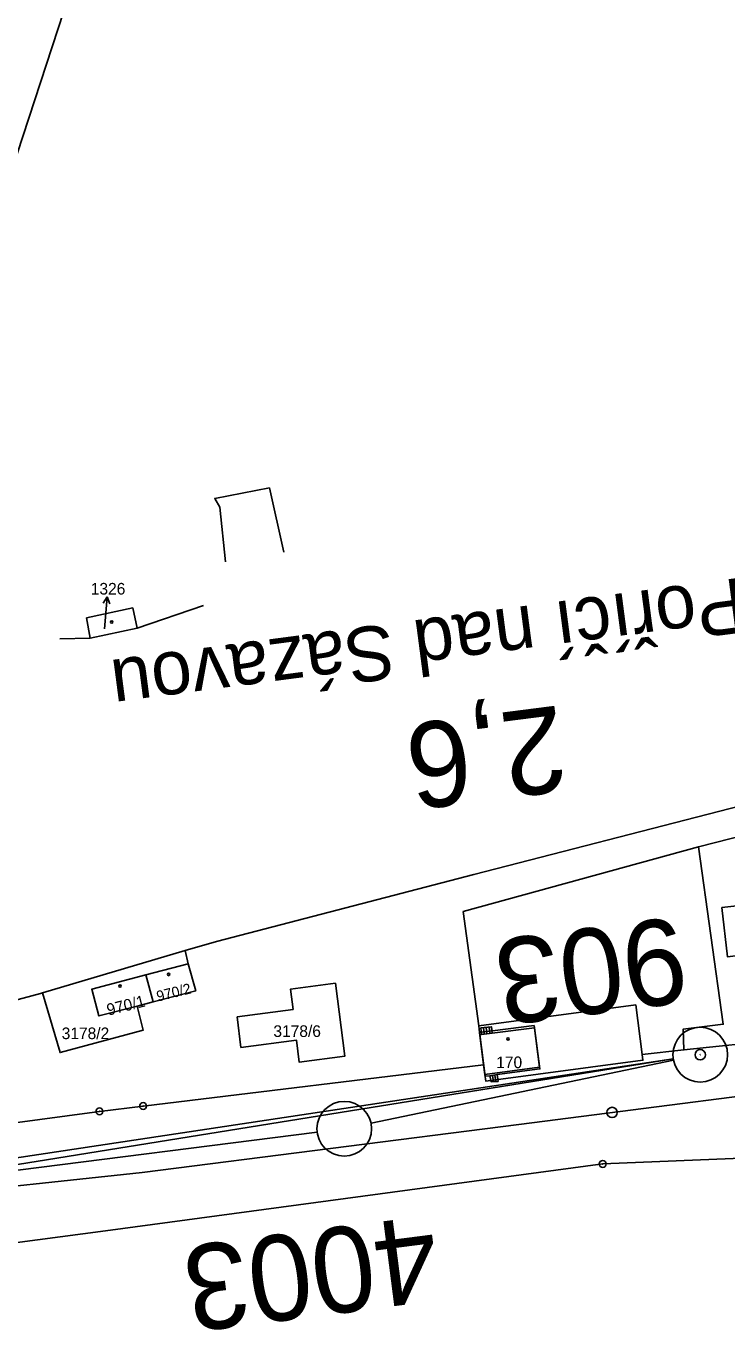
# Model space of a CAD drawing. Extents: x -728802 to -728097, y -1073200 to -1072700.
# Drawn here: x -728446.1 to -728343.6, y -1073063.9 to -1072873.2 of the extents above; entities that cross this region are included whole.
import ezdxf

# ---------------------------------------------------------------- set-up
doc = ezdxf.new("R2010")
doc.units = 0
for name, color, linetype in [('A5_JŽM', 7, 'Continuous'), ('body_ZBP', 7, 'Continuous'), ('body_ZBP-zničený', 7, 'Continuous'), ('body_ZBP_nový', 7, 'Continuous'), ('Hranice parcel', 7, 'Continuous'), ('Pop  PČ popisy', 7, 'Continuous'), ('ZZZ_popisky', 7, 'Continuous')]:
    doc.layers.add(name, color=color, linetype=linetype)

msp = doc.modelspace()

# ---------------------------------------------------------------- linework, layer by layer
at = {"layer": 'A5_JŽM'}
for p, q in [((-728379.18, -1073019.6), (-728379.08, -1073020.53)), ((-728378.76, -1073019.55), (-728378.66, -1073020.49)), ((-728378.35, -1073019.5), (-728378.25, -1073020.44)), ((-728377.69, -1073027.49), (-728377.84, -1073026.57)), ((-728377.34, -1073027.46), (-728377.5, -1073026.52))]:
    msp.add_line(p, q, dxfattribs=at)
for points in [[(-728320.8, -1073026.91), (-728374.01, -1073033.72), (-728429.1, -1073040.75), (-728461.93, -1073044.27), (-728481.2, -1073044.81), (-728499.35, -1073043.65), (-728506.01, -1073042.74), (-728514.57, -1073041.33), (-728535.85, -1073036), (-728561.35, -1073026.11), (-728583.96, -1073013.52), (-728603.76, -1072998.89), (-728619.19, -1072984.42), (-728634.19, -1072966.82), (-728646.08, -1072949.19), (-728656.18, -1072930.07), (-728664.99, -1072910.23), (-728668.63, -1072901.81), (-728681.25, -1072876.02), (-728691.89, -1072859.66)], [(-728498.81, -1073037.92), (-728499.78, -1073032.61), (-728497.54, -1073030.15), (-728493.68, -1073027.94), (-728443.97, -1073014.59), (-728443.68, -1073014.51), (-728441.09, -1073023.23), (-728428.92, -1073019.94), (-728429.82, -1073016.43), (-728427.49, -1073015.84), (-728421.24, -1073014.23), (-728422.34, -1073010.27), (-728422.77, -1073008.34), (-728418.21, -1073007), (-728380.57, -1072997.2), (-728343.1, -1072987.57), (-728330.49, -1072984.52), (-728326.79, -1072988.95)], [(-728347.72, -1072993.16), (-728382.13, -1073002.62), (-728379.86, -1073019.33), (-728379.76, -1073020.32), (-728379.15, -1073025.03)], [(-728379.15, -1073025.03), (-728378.98, -1073026.45), (-728378.8, -1073027.41), (-728355.85, -1073024.35), (-728355.97, -1073023.5), (-728349.85, -1073022.84), (-728349.94, -1073019.8), (-728344.1, -1073019.09), (-728347.72, -1072993.16)], [(-728379.69, -1073020.59), (-728379.44, -1073020.57), (-728377.87, -1073020.4), (-728371.69, -1073019.62), (-728370.92, -1073025.62), (-728377.14, -1073026.45), (-728378.22, -1073026.64), (-728378.91, -1073026.7), (-728379.69, -1073020.59)], [(-728379.57, -1073019.64), (-728378.04, -1073019.45), (-728378, -1073019.46)], [(-728379.57, -1073019.64), (-728378, -1073019.46), (-728377.87, -1073020.4)], [(-728377.87, -1073020.4), (-728379.44, -1073020.57), (-728379.57, -1073019.64)], [(-728378.22, -1073026.64), (-728377.14, -1073026.45), (-728377.01, -1073027.44)], [(-728377.01, -1073027.44), (-728378.03, -1073027.52), (-728378.22, -1073026.64)], [(-728378.03, -1073027.52), (-728377.03, -1073027.45), (-728377.01, -1073027.44)], [(-728327.13, -1073038.08), (-728361.73, -1073039.5), (-728434.43, -1073049.27), (-728470.97, -1073054.08), (-728490.19, -1073055.04), (-728500.77, -1073053.31), (-728499.61, -1073049.44), (-728498.79, -1073046.71), (-728497.84, -1073043.2), (-728498.81, -1073037.92)]]:
    msp.add_lwpolyline(points, dxfattribs=at)
msp.add_circle((-728360.36, -1073031.98), 0.75, dxfattribs=at)
at = {"layer": 'body_ZBP'}
for p, q in [((-728517.38, -1073049.14), (-728351.41, -1073024.13)), ((-728498.14, -1073047.73), (-728351.41, -1073024.17)), ((-728351.37, -1073024.35), (-728395.6, -1073033.55)), ((-728517.36, -1073049.24), (-728403.49, -1073034.86))]:
    msp.add_line(p, q, dxfattribs=at)
msp.add_circle((-728347.46, -1073023.54), 4, dxfattribs=at)
at = {"layer": 'body_ZBP-zničený'}
msp.add_line((-728347.41, -1073023.53), (-728347.51, -1073023.54), dxfattribs=at)
msp.add_circle((-728347.46, -1073023.54), 0.756, dxfattribs=at)
at = {"layer": 'body_ZBP_nový'}
msp.add_circle((-728399.52, -1073034.36), 4, dxfattribs=at)
at = {"layer": 'Hranice parcel'}
for p, q in [((-728416.91, -1072951.52), (-728417.74, -1072943.54)), ((-728437.24, -1072959.69), (-728430.47, -1072958.23)), ((-728434.2, -1072956.63), (-728434.79, -1072957.58)), ((-728434.46, -1072959.62), (-728434.2, -1072956.63)), ((-728434.2, -1072956.63), (-728433.79, -1072957.67)), ((-728430.47, -1072958.23), (-728429.83, -1072961.22)), ((-728420.13, -1072957.92), (-728429.83, -1072961.22)), ((-728436.7, -1072962.66), (-728437.24, -1072959.69)), ((-728434.61, -1072961.31), (-728434.46, -1072959.62)), ((-728429.83, -1072961.22), (-728436.7, -1072962.66)), ((-728441.11, -1072962.77), (-728436.7, -1072962.66)), ((-728418.21, -1073007), (-728422.77, -1073008.34)), ((-728422.77, -1073008.34), (-728443.68, -1073014.51)), ((-728422.34, -1073010.27), (-728422.77, -1073008.34)), ((-728428.53, -1073011.87), (-728422.34, -1073010.27)), ((-728427.49, -1073015.84), (-728428.53, -1073011.87)), ((-728443.68, -1073014.51), (-728443.97, -1073014.59)), ((-728427.49, -1073015.84), (-728429.82, -1073016.43)), ((-728379.76, -1073020.32), (-728371.74, -1073019.3)), ((-728371.74, -1073019.3), (-728370.95, -1073025.34)), ((-728349.85, -1073022.84), (-728355.97, -1073023.5)), ((-728379.15, -1073025.03), (-728428.94, -1073031.04)), ((-728370.95, -1073025.34), (-728378.98, -1073026.45))]:
    msp.add_line(p, q, dxfattribs=at)
for points in [[(-728417.74, -1072943.54), (-728418.47, -1072942.26), (-728410.47, -1072940.72), (-728408.37, -1072950.11)], [(-728343.1, -1072987.57), (-728380.57, -1072997.2), (-728418.21, -1073007)], [(-728326.79, -1072988.95), (-728333.76, -1072989.63), (-728347.72, -1072993.16)], [(-728379.86, -1073019.33), (-728382.13, -1073002.62), (-728347.72, -1072993.16)], [(-728347.72, -1072993.16), (-728344.1, -1073019.09), (-728349.94, -1073019.8), (-728349.85, -1073022.84)], [(-728334.31, -1073006.83), (-728334.91, -1073001.49), (-728340.31, -1073002.1), (-728340.37, -1073001.6), (-728344.29, -1073002.04), (-728343.48, -1073009.22), (-728339.54, -1073008.76), (-728339.67, -1073007.5), (-728334.31, -1073006.83)], [(-728307.76, -1073007.16), (-728307.91, -1073016.3), (-728307.59, -1073018.47), (-728349.85, -1073022.84)], [(-728422.34, -1073010.27), (-728421.24, -1073014.23), (-728427.49, -1073015.84)], [(-728429.82, -1073016.43), (-728435.4, -1073017.87), (-728436.45, -1073013.98), (-728428.53, -1073011.87)], [(-728415.21, -1073018.01), (-728414.63, -1073022.47), (-728406.51, -1073021.4), (-728406.12, -1073024.61), (-728399.42, -1073023.75), (-728400.81, -1073013.1), (-728407.41, -1073013.97), (-728407.02, -1073016.93), (-728415.21, -1073018.01)], [(-728443.97, -1073014.59), (-728493.68, -1073027.94), (-728497.54, -1073030.15), (-728499.78, -1073032.61)], [(-728443.68, -1073014.51), (-728441.09, -1073023.23), (-728428.92, -1073019.94), (-728429.82, -1073016.43)], [(-728355.97, -1073023.5), (-728356.9, -1073016.27), (-728379.86, -1073019.33)], [(-728379.86, -1073019.33), (-728379.76, -1073020.32), (-728379.15, -1073025.03)], [(-728379.15, -1073025.03), (-728378.98, -1073026.45), (-728378.8, -1073027.41), (-728355.85, -1073024.35), (-728355.97, -1073023.5)], [(-728428.94, -1073031.04), (-728435.33, -1073031.82), (-728462.29, -1073035.43), (-728488.6, -1073038.02), (-728488.39, -1073034.38), (-728493.51, -1073034.35), (-728493.84, -1073039.37)], [(-728499.61, -1073049.44), (-728500.77, -1073053.31), (-728490.19, -1073055.04), (-728470.97, -1073054.08), (-728434.43, -1073049.27), (-728361.73, -1073039.5), (-728327.13, -1073038.08)]]:
    msp.add_lwpolyline(points, dxfattribs=at)
for centre, radius in [((-728433.54, -1072960.33), 0.175), ((-728425.21, -1073011.82), 0.175), ((-728432.32, -1073013.52), 0.175), ((-728375.57, -1073021.24), 0.175), ((-728428.94, -1073031.04), 0.5), ((-728435.33, -1073031.82), 0.5), ((-728435.33, -1073031.82), 0.0303), ((-728428.94, -1073031.04), 0.0303), ((-728361.73, -1073039.5), 0.5), ((-728361.73, -1073039.5), 0.0303)]:
    msp.add_circle(centre, radius, dxfattribs=at)
at = {"layer": 'ZZZ_popisky'}
msp.add_lwpolyline([(-728496.07, -1073040.51), (-728413.22, -1072787.63), (-728463.11, -1072771.29)], dxfattribs=at)

# ---------------------------------------------------------------- texts
at = {"layer": 'A5_JŽM'}
for s, height, rotation, p in [('zast. Poříčí nad Sázavou', 8, 187.4528, (-728316.1, -1072950.5)), ('2,6', 12.5, 187.2914, (-728367.97, -1072972.46))]:
    msp.add_text(s, height=height, rotation=rotation, dxfattribs=at).set_placement(p)
at = {"layer": 'body_ZBP'}
msp.add_text('903', height=12.5, rotation=187.2914, dxfattribs=at).set_placement((-728350.36, -1073003.35))
at = {"layer": 'body_ZBP_nový'}
msp.add_text('4003', height=12.5, rotation=187.2914, dxfattribs=at).set_placement((-728386.67, -1073046.97))
at = {"layer": 'Hranice parcel'}
for s, height, p in [('970/2', 1.53, (-728426.77, -1073015.79)), ('970/1', 1.7, (-728434.03, -1073017.84))]:
    msp.add_text(s, height=height, rotation=14, dxfattribs=at).set_placement(p)
for s, p in [('3178/6', (-728409.89, -1073020.95)), ('3178/2', (-728440.85, -1073021.27)), ('170', (-728377.3, -1073025.51))]:
    msp.add_text(s, height=1.7, dxfattribs=at).set_placement(p)
at = {"layer": 'Pop  PČ popisy'}
msp.add_text('1326', height=1.7, dxfattribs=at).set_placement((-728436.6, -1072956.31))

doc.saveas('drawing.dxf')
